Omron CX-Programmer project 新工程 (CX-Programmer 9.62)

# PLC 新PLC1: CJ2M CPU31
I/O table (CPU CJ2M-CPU31): rack 0 slot 0 CJ1W-SCU41-V1; rack 0 slot 11 CJ2M-EIP21

## Global symbols (name address type ; comment)
1509.15 BOOL  ; 协议执行中
1559.14 BOOL  ; 故障
W0.00 BOOL  ; 读允许
W0.01 BOOL  ; 写允许

## Program 新程序1 (cyclic task 0)
; SCU41单元号：0

### Section 段1

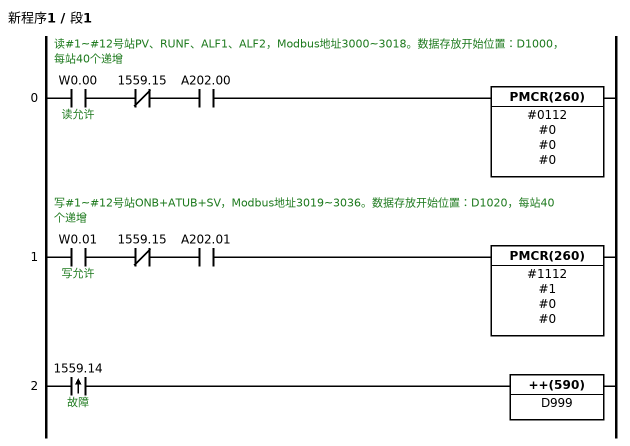
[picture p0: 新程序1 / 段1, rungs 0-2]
; rung 0: 读#1~#12号站PV、RUNF、ALF1、ALF2，Modbus地址3000~3018。数据存放开始位置：D1000，每站40个递增
LD W0.00  ; 读允许
ANDNOT 1559.15
AND A202.00
PMCR(260) #0112 #0 #0 #0
; rung 1: 写#1~#12号站ONB+ATUB+SV，Modbus地址3019~3036。数据存放开始位置：D1020，每站40个递增
LD W0.01  ; 写允许
ANDNOT 1559.15
AND A202.01
PMCR(260) #1112 #1 #0 #0
; rung 2
@LD 1559.14  ; 故障
++(590) D999

### Section END
; rung 0
END(001)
